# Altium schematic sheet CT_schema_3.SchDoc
size 276 x 169 mm
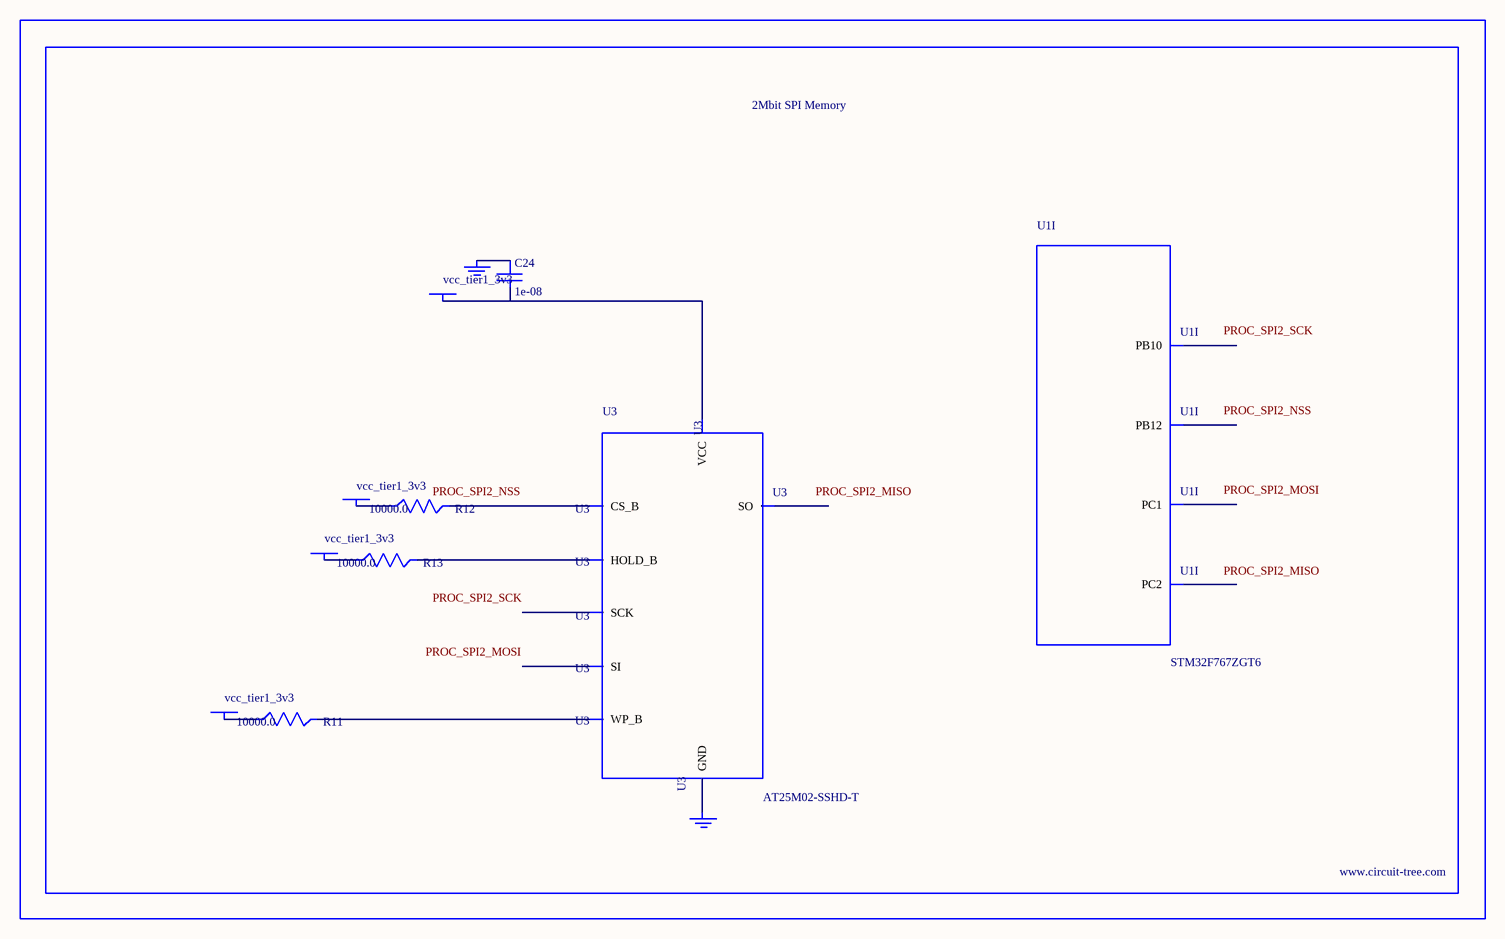
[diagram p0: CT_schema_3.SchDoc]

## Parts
BORDER2  (no value)
C24  1e-08  [C0402]
GND_INSTANCE_2_0  (no value)
GND_INSTANCE_2_1  (no value)
POWER_INSTANCE_2_0  vcc_tier1_3v3
POWER_INSTANCE_2_1  vcc_tier1_3v3
POWER_INSTANCE_2_2  vcc_tier1_3v3
POWER_INSTANCE_2_3  vcc_tier1_3v3
R11  10000.0  [R0603]
R12  10000.0  [R0603]
R13  10000.0  [R0603]
U1  STM32F767ZGT6  [LQFP144]  (part I of 13)
U3  AT25M02-SSHD-T  [SOIC-8]

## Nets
NetC24_1: C24.1 GND_INSTANCE_2_0.0(GND)
NetC24_2: C24.2 POWER_INSTANCE_2_3.0(PWR) U3.8(VCC)
NetGND_INSTANCE_2_1_0: GND_INSTANCE_2_1.0(GND) U3.4(GND)
NetPOWER_INSTANCE_2_0_0: POWER_INSTANCE_2_0.0(PWR) R12.1
NetPOWER_INSTANCE_2_1_0: POWER_INSTANCE_2_1.0(PWR) R11.1
NetPOWER_INSTANCE_2_2_0: POWER_INSTANCE_2_2.0(PWR) R13.1
NetR11_2: R11.2 U3.3(WP_B)
NetR12_2: R12.2 U3.1(CS_B)
NetR13_2: R13.2 U3.7(HOLD_B)

Not connected (* = marked no-connect by the designer): U1 27(PC1) 28(PC2) 69(PB10) 73(PB12); U3 2(SO) 5(SI) 6(SCK)

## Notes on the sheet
- Labels drawn without touching a wire or pin: PROC_SPI2_MISO, PROC_SPI2_MOSI, PROC_SPI2_NSS, PROC_SPI2_SCK

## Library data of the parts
BORDER2 = BORDER_PAGE2
C24 = C0402C103K3RAC
GND_INSTANCE_2_0 GND_INSTANCE_2_1 = GND
POWER_INSTANCE_2_0-POWER_INSTANCE_2_3 = PWR
R11-R13 = RC0603JR-0710KL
